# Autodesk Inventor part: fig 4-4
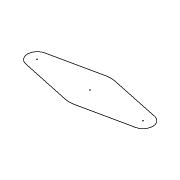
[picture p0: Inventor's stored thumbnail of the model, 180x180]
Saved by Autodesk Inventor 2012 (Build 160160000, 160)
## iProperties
Created: 2005-02
Part Number: fig 4-4
Document SubType Name: Modeling
Designer: CADCIM
Manufacturer: Standard
Standards Organization: Custom
Density: 1 g/cm^3
Material: Default
Author: CADCIM
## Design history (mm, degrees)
sketch "Sketch1"
  geometry: L1 (-33.874, 5.844)-(-2.722, 12.469); L2 (2.595, 12.472)-(33.871, 5.852); L3 (-33.884, -5.902)-(-2.745, -12.585); L4 (2.595, -12.592)-(33.871, -5.972); A1 r 6.006 centre (-32.624, -0.03) between (-33.874, 5.844) and (-33.884, -5.902); A2 r 6.043 centre (32.619, -0.06) between (33.871, -5.972) and (33.871, 5.852); A3 r 12.81 centre (-0.057, -0.06) between (-2.745, -12.585) and (2.595, -12.592); A4 r 12.81 centre (-0.057, -0.06) between (2.595, 12.472) and (-2.722, 12.469)
  constraints: 8 end point, 8 point on circle, 8 tangent, 4 centre point, 1 other
